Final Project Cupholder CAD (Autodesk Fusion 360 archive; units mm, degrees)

design "Final Project" references "Servo_motor", "Arcade Button_30mm", "EIP Cupholder PCB"
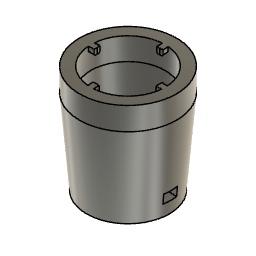
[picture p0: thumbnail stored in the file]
parameter "CupHolderBottomDiameter" = 76.2
parameter "CupHolderTopDiameter" = 88.9
parameter "CupHolderHeight" = 76.2
parameter "CupHolderThickness" = 10 comment "Only for visual CAD  purposes"
parameter "CupHolderTolerance" = 2 comment "Between cup holder and the mechanism case"
parameter "LidHeight" = 30
parameter "CupHolderCaseThickness" = 10
parameter "LockingMechanismProtrusionWidth" = 5
parameter "LockingMechanismTolerance" = 1
parameter "LockingMechanismProtrusionHeight" = 5
parameter "LockingMechanismProtrusionDistance" = 5
parameter "LockingMechanismAngle" = 20
parameter "ArcadeButtonDiameter" = 30
parameter "MirrorAttachmentCurlThickness" = 2
sketch "Sketch2" plane through (0, 0, 0) normal (0, 0, 1) x axis (1, 0, 0)
  circle C1 centre (0, 0) radius 38.1
  point P1 (0, 0)
  point P2 (0, 0)
  coincident P1 P2
  dimension "d3" diameter C1 = 76.2 (= "CupHolderBottomDiameter")
work_plane "WorkPlane1" sketch "Sketch2" AlongDistance 76.2 (= "CupHolderHeight")
sketch "Sketch3" plane through (0, 0, 76.2) normal (0, 0, 1) x axis (1, 0, 0)
  circle C1 centre (0, 0) radius 44.45
  point P1 (0, 0)
  point P2 (0, 0)
  coincident P1 P2
  dimension "d6" diameter C1 = 88.9 (= "CupHolderTopDiameter")
loft "Loft1" sketch "Sketch2" + "Sketch3"
sketch "Sketch4" plane through (0, 0, 0) normal (0, 0, 1) x axis (1, 0, 0)
  circle C1 centre (0, 0) radius 88.9
  point P1 (0, 0)
  point P2 (0, 0)
  coincident P1 P2
  dimension "d7" diameter C1 = 177.8 (= "CupHolderTopDiameter * 2")
extrude "Extrude1" new body sketch "Sketch4" along normal blind 76.2 (= "CupHolderHeight")
extrude "Extrude2" new body of existing geometry blind 10 (= "CupHolderThickness") bodies "CupHolder"
combine "Combine2"
combine "Combine1"
sketch "Sketch1" plane through (0, 0, 0) normal (0, 0, 1) x axis (1, 0, 0)
  circle C1 centre (0, 0) radius 44.45
  point P1 (0, 0)
  point P2 (0, 0)
  coincident P1 P2
  dimension "d15" diameter C1 = 88.9 (= "CupHolderTopDiameter")
extrude "Extrude1" new body sketch "Sketch1" along normal blind 76.2 (= "CupHolderHeight")
combine "Combine1"
copy_paste "CutPaste1"
offset_faces "OffsetFaces1"
extrude "Extrude2" add of existing geometry blind 30 (= "LidHeight")
shell "Shell2" innerThickness 10 (= "CupHolderThickness")
split "Split4" bodies "CupHolderCase"
sketch "Sketch4" plane through (0, 0, 96.2) normal (0, 0, -1) x axis (1, 0, 0)
  circle C1 centre (0, 0) radius 42.4431
  circle C2 centre (0, 0) radius 32.4431
extrude "Extrude4" new body sketch "Sketch4" profile of C2 along normal blind 20 (= "LidHeight - CupHolderThickness")
combine "Combine4"
sketch "Sketch5" plane through (0, 0, 76.2) normal (0, 0, -1) x axis (1, 0, 0)
  line L1 (0, -32.4431) -> (0, -36.9654)
  line L2 (3, -32.4431) -> (0, -32.4431)
  line L3 (3, -25.4431) -> (3, -32.4431)
  line L4 (0, -25.4431) -> (3, -25.4431)
  line L5 (-3, -32.4431) -> (0, -32.4431)
  line L6 (-3, -25.4431) -> (-3, -32.4431)
  line L7 (0, -25.4431) -> (-3, -25.4431)
  circle C1 centre (0, 0) radius 32.4431
  point P4 (0, -32.4431)
  point P8 (0, -32.4431)
  point P5 (3, -32.4431)
  point P9 (-3, -32.4431)
  point P6 (3, -25.4431)
  point P10 (-3, -25.4431)
  point P7 (0, -25.4431)
  point P11 (0, -25.4431)
  coincident C1 P4
  vertical L1
  tangent C1 L2
  perpendicular L1 L2
  perpendicular L2 L3
  perpendicular L3 L4
  symmetric P4 L1 P8
  symmetric L1 P5 P9
  symmetric L1 P6 P10
  symmetric L1 P7 P11
  dimension "d37" distance P4 P5 = 3 (= "LockingMechanismProtrusionWidth / 2 + LockingMechanismTolerance / 2")
  dimension "d39" distance P5 P6 = 7 (= "LockingMechanismProtrusionDistance + CupHolderTolerance")
extrude "Extrude5" cut sketch "Sketch5" profile of C1 L3 L4 L6 L7 against normal blind 20
sketch "Sketch6" plane through (0, 0, 96.2) normal (0, 0, -1) x axis (1, 0, 0)
  line L1 (3, -25.4431) -> (3, -32.3041)
  line L2 (-3, -25.4431) -> (3, -25.4431)
  line L3 (-3, -32.3041) -> (-3, -25.4431)
  line L4 (-8.702, -23.9087) -> (0, 0)
  line L5 (0, -25.4431) -> (0, 0)
  line L6 (-11.0962, -30.4865) -> (-8.702, -23.9087)
  line L7 (-3, -25.2656) -> (-3, -25.4431)
  arc A1 centre (0, 0) radius 32.4431 clockwise from (-3, -32.3041) to (3, -32.3041)
  circle C1 centre (0, 0) radius 42.4431
  arc A2 centre (0, 0) radius 25.4431 clockwise from (0, -25.4431) to (-8.702, -23.9087)
  point P9 (0, -25.4431)
  point P1 (0, 0)
  point P7 (0, 0)
  point P10 (-11.0962, -30.4865)
  point P6 (-3, -25.4431)
  point P11 (-3, -25.4431)
  point P12 (-3, -25.2656)
  midpoint L2 P9
  coincident P1 P7
  coincident A1 P10
  parallel L4 L6
  coincident P6 P11
  coincident A2 P12
  perpendicular L2 L7
  dimension "d43" angle L4 L5 = 20 (= "LockingMechanismAngle")
extrude "Extrude6" cut sketch "Sketch6" profile of A1 L3 A2 L6 L7 along normal blind 6 (= "LockingMechanismProtrusionHeight + LockingMechanismTolerance")
extrude "Extrude7" cut sketch "Sketch6" profile of L2 A2 L7 along normal blind 20
sketch "Sketch7" plane through (0, 0, 0) normal (0.9397, 0.342, 0) x axis (-0.342, 0.9397, 0)
  line L1 (25.4431, 96.2) -> (32.4431, 96.2)
  line L2 (25.4431, 90.2) -> (25.4431, 96.2)
  line L3 (32.4431, 90.2) -> (25.4431, 90.2)
  line L4 (32.4431, 96.2) -> (32.4431, 90.2)
  line L5 (32.4431, 91.2) -> (32.4431, 90.2)
  line L6 (25.4431, 91.2) -> (32.4431, 91.2)
  point P5 (32.4431, 90.2)
  point P6 (32.4431, 90.2)
  point P7 (32.4431, 91.2)
  point P8 (25.4431, 91.2)
  coincident P5 P6
  coincident L4 P7
  coincident L2 P8
  perpendicular L2 L6
  dimension "d48" distance P6 P7 = 1 (= "LockingMechanismTolerance")
loft "Loft3" sketch "Sketch7"
circular_pattern "C-Pattern1" TotalAngle 360
fillet "Fillet2" radius 1 1
sketch "Sketch8" plane through (0, 0, 96.2) normal (0, 0, 1) x axis (-1, 0, 0)
  line L1 (2.2086, -32.4642) -> (-0.2913, -32.4418)
  line L2 (2.2535, -27.4644) -> (2.2086, -32.4642)
  line L3 (-0.4431, -27.4402) -> (2.2535, -27.4644)
  line L4 (-0.4431, -27.4402) -> (-0.2913, -32.4418)
  line L5 (-2.7852, -32.6157) -> (-0.2913, -32.4418)
  line L6 (-3.1332, -27.6279) -> (-2.7852, -32.6157)
  line L7 (-0.4431, -27.4402) -> (-3.1332, -27.6279)
  circle C1 centre (0, 0) radius 32.4431
  circle C2 centre (0, 0) radius 42.4431
  point P3 (-0.2913, -32.4418)
  point P7 (-0.2913, -32.4418)
  point P4 (2.2086, -32.4642)
  point P8 (-2.7852, -32.6157)
  point P5 (2.2535, -27.4644)
  point P9 (-3.1332, -27.6279)
  point P6 (-0.4431, -27.4402)
  point P10 (-0.4431, -27.4402)
  coincident C1 P3
  tangent C1 L1
  perpendicular L1 L2
  perpendicular L2 L3
  symmetric P3 L4 P7
  symmetric P4 L4 P8
  symmetric P5 L4 P9
  symmetric P6 L4 P10
  dimension "d51" distance P3 P4 = 2.5 (= "LockingMechanismProtrusionWidth / 2")
  dimension "d52" distance P4 P5 = 5
extrude "Extrude8" add sketch "Sketch8" profile of C1 L2 L3 L6 L7 no distance stored
fillet "Fillet1" radius 1
circular_pattern "C-Pattern2" TotalAngle 360
sketch "Sketch9" plane through (0, 0, 106.2) normal (0, 0, 1) x axis (-1, 0, 0)
  line L1 (-13.5367, -40.2265) -> (0, 0)
  line L2 (-0.4435, -42.4408) -> (0, 0)
  line L3 (0, 0) -> (-7.0772, -41.8489)
  line L4 (-19.6113, -115.9654) -> (-7.0772, -41.8489)
  curve K1 (-7.4119, -43.8277) -> (-0.4435, -42.4408)
  curve K2 (-0.847, -42.4391) -> (-0.04, -42.4424)
  line L5 (-10.6726, -43.2763) -> (-7.4119, -43.8277)
  curve K3 (-9.0422, -43.552) -> (-5.7815, -44.1034)
  curve K4 (-7.4119, -43.8277) -> (-13.5367, -40.2265)
  curve K5 (-13.1551, -40.3576) -> (-13.9183, -40.0954)
  curve K6 (-5.7815, -44.1034) -> (-9.0422, -43.552)
  circle C1 centre (0, 0) radius 42.4431
  arc A1 centre (0, 0) radius 42.4431 clockwise from (-0.4435, -42.4408) to (-13.5367, -40.2265)
  point P5 (-0.4435, -42.4408)
  point P1 (0, 0)
  point P3 (0, 0)
  point P6 (-7.0772, -41.8489)
  point P7 (-7.0772, -41.8489)
  point P8 (0, 0)
  point P9 (-7.0772, -41.8489)
  point P12 (-7.4119, -43.8277)
  point P17 (-9.0422, -43.552)
  point P18 (-13.5367, -40.2265)
  point P11 (-4.9088, -86.9573)
  point P19 (-23.9577, -83.7359)
  point P20 (-7.4119, -43.8277)
  point P13 (-0.04, -42.4424)
  point P21 (-13.9183, -40.0954)
  point P14 (-0.847, -42.4391)
  point P22 (-13.1551, -40.3576)
  point P16 (-5.7815, -44.1034)
  point P23 (-9.0422, -43.552)
  point P24 (-5.7815, -44.1034)
  coincident C1 P5
  coincident P1 P3
  midpoint A1 P6
  coincident P6 P7
  coincident P1 P8
  coincident P6 P9
  parallel L3 L4
  coincident L4 P12
  midpoint P5 K2
  perpendicular L4 L5
  midpoint P12 K3
  midpoint L5 P17
  parallel L5 K3
  symmetric P5 L4 P18
  symmetric L4 P11 P19
  symmetric L4 P12 P20
  symmetric L4 P13 P21
  symmetric L4 P14 P22
  symmetric L4 P16 P23
  symmetric L4 P17 P24
  dimension "d64" angle L1 L2 = 18 (= "( 360 / NumGripsTopLid ) * 1 deg")
  dimension "d153" distance P8 P12 = 44.45 (= "CupHolderTopDiameter / 2")
extrude "Extrude9" new body sketch "Sketch9" profile of C1 K1 K4 against normal blind 10
combine "Combine6"
circular_pattern "C-Pattern4" TotalAngle 360
component_from_bodies "Body->Comp1"
component_from_bodies "Body->Comp2"
fillet "Fillet1" radius 1
fillet "Fillet2" radius 1
sketch "Sketch10" plane through (0, 0, 76.2) normal (0, 0, -1) x axis (1, 0, 0)
  line L1 (24.1136, -4) -> (31.1876, -4)
  line L2 (24.4431, 4) -> (24.4431, 0)
  line L3 (31.1876, 4) -> (24.4431, 4)
  line L4 (4, 24.1136) -> (4, 31.1876)
  line L5 (-4, 24.4431) -> (0, 24.4431)
  line L6 (-4, 31.1876) -> (-4, 24.4431)
  line L7 (-24.1136, 4) -> (-31.1876, 4)
  line L8 (-24.4431, -4) -> (-24.4431, 0)
  line L9 (-31.1876, -4) -> (-24.4431, -4)
  line L10 (-4, -24.1136) -> (-4, -31.1876)
  line L11 (4, -24.4431) -> (0, -24.4431)
  line L12 (4, -31.1876) -> (4, -24.4431)
  arc A1 centre (0, 0) radius 24.4431 clockwise from (24.4431, 0) to (24.1136, -4)
  arc A2 centre (0, 0) radius 31.4431 clockwise from (4, 31.1876) to (31.1876, 4)
  arc A3 centre (0, 0) radius 24.4431 clockwise from (0, 24.4431) to (4, 24.1136)
  arc A4 centre (0, 0) radius 31.4431 clockwise from (-31.1876, 4) to (-4, 31.1876)
  arc A5 centre (0, 0) radius 24.4431 clockwise from (-24.4431, 0) to (-24.1136, 4)
  arc A6 centre (0, 0) radius 31.4431 clockwise from (-4, -31.1876) to (-31.1876, -4)
  arc A7 centre (0, 0) radius 24.4431 clockwise from (0, -24.4431) to (-4, -24.1136)
  arc A8 centre (0, 0) radius 31.4431 clockwise from (31.1876, -4) to (4, -31.1876)
  circle C1 centre (0, 0) radius 22.5
  concentric A1 C1
  dimension "d155" diameter C1 = 45 (= "ArcadeButtonDiameter + 15 mm")
extrude "Extrude1" cut sketch "Sketch10" profile of C1 against normal blind 20
fillet "Fillet3" radius 1
fillet "Fillet4" radius 1
sketch "Sketch11" plane through (0, 0, 96.2) normal (0, 0, -1) x axis (1, 0, 0)
  circle C1 centre (0, 0) radius 21.5
  circle C2 centre (0, 0) radius 15
  point P1 (0, 0)
  point P3 (0, 0)
  coincident P1 P3
  dimension "d82" diameter C2 = 30 (= "ArcadeButtonDiameter")
extrude "Extrude2" cut sketch "Sketch11" profile of C2 against normal blind 10
component_insert "Component Insert1"
joint "Assemble1" alignAngle 0 alignOffsetX 0 alignOffsetY 0 alignOffsetZ 0
as_built_joint "As-built1" OffsetX 0 OffsetY 0 OffsetZ 0 AngleZ 0 AngleMaximum 0
joint "Assemble1" alignAngle 0 alignOffsetX 0 alignOffsetY 0 alignOffsetZ -130 DistanceMaximum 0 DistanceRest 0
base_feature "Base Feature1"
base_feature "Base Feature1"
base_feature "Base Feature1"
base_feature "Base Feature1"
base_feature "Base Feature1"
base_feature "Base Feature1"
base_feature "Base Feature1"
base_feature "Base Feature1"
base_feature "Base Feature1"
base_feature "Base Feature1"
base_feature "Base Feature1"
sketch "Sketch4" plane through (-0.0164, 0, -21.4157) normal (-0.0008, 0, -1) x axis (0, -1, 0)
  line L1 (-46.2621, -82.9366) -> (-46.2621, -20.9366)
  line L2 (51.0689, -82.9366) -> (-46.2621, -82.9366)
  line L3 (51.0689, -20.9366) -> (51.0689, -82.9366)
  line L4 (-46.2621, -20.9366) -> (51.0689, -20.9366)
  line L5 (8.573, -42.2771) -> (8.573, -31.2771)
  line L6 (-4.427, -44.2771) -> (6.573, -44.2771)
  line L7 (-6.427, -31.2771) -> (-6.427, -42.2771)
  line L8 (6.573, -29.2771) -> (-4.427, -29.2771)
  line L9 (-123.9966, -211.3616) -> (128.8034, -211.3616)
  line L10 (-123.9966, -20.9366) -> (-123.9966, -211.3616)
  line L11 (128.8034, -20.9366) -> (-123.9966, -20.9366)
  line L12 (128.8034, -211.3616) -> (128.8034, -20.9366)
  arc A1 centre (6.573, -42.2771) radius 2 clockwise from (8.573, -42.2771) to (6.573, -44.2771)
  arc A2 centre (-4.427, -42.2771) radius 2 clockwise from (-4.427, -44.2771) to (-6.427, -42.2771)
  arc A3 centre (-4.427, -31.2771) radius 2 clockwise from (-6.427, -31.2771) to (-4.427, -29.2771)
  arc A4 centre (6.573, -31.2771) radius 2 clockwise from (6.573, -29.2771) to (8.573, -31.2771)
  point P22 (2.4034, -20.9366)
  point P23 (2.4034, -20.9366)
  point P18 (128.8034, -211.3616)
  point P19 (-123.9966, -211.3616)
  point P20 (-123.9966, -20.9366)
  horizontal L9
  vertical L10
  horizontal L11
  vertical L12
  midpoint L11 P22
  midpoint L4 P23
  coincident P22 P23
  dimension "d128" distance P18 P19 = 252.8
  dimension "d129" distance P19 P20 = 190.425
extrude "Extrude2" new body sketch "Sketch4" profile of L1 L2 L3 L9 L10 L11 L12 against normal blind 2
combine "Combine3"
copy_paste_bodies "CutPasteBodies1"
remove_body "RemoveBody1"
sketch "Sketch5" plane through (-0.0164, 0, -21.4157) normal (-0.0008, 0, -1) x axis (0, -1, 0)
  line L1 (8.573, -42.2771) -> (8.573, -31.2771)
  line L2 (-4.427, -44.2771) -> (6.573, -44.2771)
  line L3 (-6.427, -31.2771) -> (-6.427, -42.2771)
  line L4 (6.573, -29.2771) -> (-4.427, -29.2771)
  line L5 (-123.9966, -20.9366) -> (128.8034, -20.9366)
  line L6 (-123.9966, -211.3616) -> (-123.9966, -20.9366)
  line L7 (128.8034, -211.3616) -> (-123.9966, -211.3616)
  line L8 (128.8034, -20.9366) -> (128.8034, -211.3616)
  line L9 (121.8034, -211.3616) -> (128.8034, -211.3616)
  line L10 (121.8034, -204.3616) -> (121.8034, -211.3616)
  line L11 (128.8034, -204.3616) -> (121.8034, -204.3616)
  line L12 (128.8034, -211.3616) -> (128.8034, -204.3616)
  arc A1 centre (6.573, -42.2771) radius 2 clockwise from (8.573, -42.2771) to (6.573, -44.2771)
  arc A2 centre (-4.427, -42.2771) radius 2 clockwise from (-4.427, -44.2771) to (-6.427, -42.2771)
  arc A3 centre (-4.427, -31.2771) radius 2 clockwise from (-6.427, -31.2771) to (-4.427, -29.2771)
  arc A4 centre (6.573, -31.2771) radius 2 clockwise from (6.573, -29.2771) to (8.573, -31.2771)
  circle C1 centre (121.8034, -204.3616) radius 2
  point P17 (128.8034, -211.3616)
  point P18 (128.8034, -211.3616)
  point P20 (121.8034, -204.3616)
  point P22 (121.8034, -204.3616)
  point P21 (128.8034, -204.3616)
  point P19 (121.8034, -211.3616)
  horizontal L9
  vertical L10
  horizontal L11
  vertical L12
  coincident P17 P18
  coincident P20 P22
  dimension "d132" distance P18 P21 = 7
  dimension "d133" distance P18 P19 = 7
  dimension "d134" diameter C1 = 4
extrude "Extrude1" cut sketch "Sketch5" profile of C1 against normal blind 2
work_plane "WorkPlane3"
work_plane "WorkPlane4"
mirror "Mirror1" mirrorStitchTolerance 0.1
mirror "Mirror2" mirrorStitchTolerance 0.1
extrude "Extrude2" cut of existing geometry blind -0.85 (= "-( 2 mm - 1.15 mm )")
sketch "Sketch6" plane through (-0.0157, 0, -20.5657) normal (-0.0008, 0, -1) x axis (0, -1, 0)
  line L1 (8.573, -42.2771) -> (8.573, -31.2771)
  line L2 (-4.427, -44.2771) -> (6.573, -44.2771)
  line L3 (-6.427, -31.2771) -> (-6.427, -42.2771)
  line L4 (6.573, -29.2771) -> (-4.427, -29.2771)
  line L5 (-123.9966, -20.9366) -> (128.8034, -20.9366)
  line L6 (-123.9966, -211.3616) -> (-123.9966, -20.9366)
  line L7 (128.8034, -211.3616) -> (-123.9966, -211.3616)
  line L8 (128.8034, -20.9366) -> (128.8034, -211.3616)
  line L9 (-123.9966, -211.3616) -> (128.8034, -211.3616)
  line L10 (-123.9966, -20.9366) -> (-123.9966, -211.3616)
  line L11 (128.8034, -20.9366) -> (-123.9966, -20.9366)
  line L12 (128.8034, -211.3616) -> (128.8034, -20.9366)
  line L13 (-98.9966, -185.8616) -> (103.8034, -185.8616)
  line L14 (-98.9966, -46.4366) -> (-98.9966, -185.8616)
  line L15 (103.8034, -46.4366) -> (-98.9966, -46.4366)
  line L16 (103.8034, -185.8616) -> (103.8034, -46.4366)
  line L17 (-98.9966, -46.4366) -> (103.8034, -185.8616)
  line L18 (103.8034, -46.4366) -> (-98.9966, -185.8616)
  line L19 (-123.9966, -20.9366) -> (128.8034, -211.3616)
  line L20 (128.8034, -20.9366) -> (-123.9966, -211.3616)
  circle C1 centre (-116.9966, -27.9366) radius 2
  circle C2 centre (-116.9966, -204.3616) radius 2
  circle C3 centre (121.8034, -27.9366) radius 2
  circle C4 centre (121.8034, -204.3616) radius 2
  arc A1 centre (6.573, -42.2771) radius 2 clockwise from (8.573, -42.2771) to (6.573, -44.2771)
  arc A2 centre (-4.427, -42.2771) radius 2 clockwise from (-4.427, -44.2771) to (-6.427, -42.2771)
  arc A3 centre (-4.427, -31.2771) radius 2 clockwise from (-6.427, -31.2771) to (-4.427, -29.2771)
  arc A4 centre (6.573, -31.2771) radius 2 clockwise from (6.573, -29.2771) to (8.573, -31.2771)
  point P19 (-123.9966, -20.9366)
  point P24 (-123.9966, -20.9366)
  point P21 (128.8034, -211.3616)
  point P22 (128.8034, -211.3616)
  point P30 (2.4034, -116.1491)
  point P31 (2.4034, -116.1491)
  point P26 (103.8034, -185.8616)
  point P27 (-98.9966, -185.8616)
  point P29 (103.8034, -46.4366)
  horizontal L9
  vertical L10
  horizontal L11
  vertical L12
  coincident P19 P24
  coincident P21 P22
  horizontal L13
  vertical L14
  horizontal L15
  vertical L16
  midpoint L18 P30
  midpoint L20 P31
  coincident P30 P31
  dimension "d143" distance P26 P27 = 202.8
  dimension "d144" distance P26 P29 = 139.425
extrude "Extrude3" new body sketch "Sketch6" profile of C1 C2 C3 C4 L1 A1 L2 A2 L3 A3 L4 A4 L5 L6 L7 L8 L9 L10 L11 L12 L13 L14 L15 L16 along normal blind 1.125
extrude "Extrude4" new body sketch "Sketch6" profile of L13 L14 L15 L16 along normal blind 1.125
move "Move1"
sketch "Sketch7" plane through (-0.0157, 0, -20.5657) normal (-0.0008, 0, -1) x axis (0, -1, 0)
  line L1 (8.573, -42.2771) -> (8.573, -31.2771)
  line L2 (-4.427, -44.2771) -> (6.573, -44.2771)
  line L3 (-6.427, -31.2771) -> (-6.427, -42.2771)
  line L4 (6.573, -29.2771) -> (-4.427, -29.2771)
  line L5 (-123.9966, -20.9366) -> (128.8034, -20.9366)
  line L6 (-123.9966, -211.3616) -> (-123.9966, -20.9366)
  line L7 (128.8034, -211.3616) -> (-123.9966, -211.3616)
  line L8 (128.8034, -20.9366) -> (128.8034, -211.3616)
  line L9 (-123.9966, -211.3616) -> (128.8034, -211.3616)
  line L10 (-123.9966, -20.9366) -> (-123.9966, -211.3616)
  line L11 (128.8034, -20.9366) -> (-123.9966, -20.9366)
  line L12 (128.8034, -211.3616) -> (128.8034, -20.9366)
  line L13 (-107.0466, -194.4116) -> (111.8534, -194.4116)
  line L14 (-107.0466, -37.8866) -> (-107.0466, -194.4116)
  line L15 (111.8534, -37.8866) -> (-107.0466, -37.8866)
  line L16 (111.8534, -194.4116) -> (111.8534, -37.8866)
  line L17 (-107.0466, -37.8866) -> (111.8534, -194.4116)
  line L18 (111.8534, -37.8866) -> (-107.0466, -194.4116)
  line L19 (-123.9966, -20.9366) -> (128.8034, -211.3616)
  line L20 (128.8034, -20.9366) -> (-123.9966, -211.3616)
  circle C1 centre (-116.9966, -27.9366) radius 2
  circle C2 centre (-116.9966, -204.3616) radius 2
  circle C3 centre (121.8034, -27.9366) radius 2
  circle C4 centre (121.8034, -204.3616) radius 2
  arc A1 centre (6.573, -42.2771) radius 2 clockwise from (8.573, -42.2771) to (6.573, -44.2771)
  arc A2 centre (-4.427, -42.2771) radius 2 clockwise from (-4.427, -44.2771) to (-6.427, -42.2771)
  arc A3 centre (-4.427, -31.2771) radius 2 clockwise from (-6.427, -31.2771) to (-4.427, -29.2771)
  arc A4 centre (6.573, -31.2771) radius 2 clockwise from (6.573, -29.2771) to (8.573, -31.2771)
  point P19 (-123.9966, -20.9366)
  point P24 (-123.9966, -20.9366)
  point P21 (128.8034, -211.3616)
  point P22 (128.8034, -211.3616)
  point P30 (2.4034, -116.1491)
  point P31 (2.4034, -116.1491)
  point P26 (111.8534, -194.4116)
  point P27 (-107.0466, -194.4116)
  point P29 (111.8534, -37.8866)
  horizontal L9
  vertical L10
  horizontal L11
  vertical L12
  coincident P19 P24
  coincident P21 P22
  horizontal L13
  vertical L14
  horizontal L15
  vertical L16
  midpoint L18 P30
  midpoint L20 P31
  coincident P30 P31
  dimension "d149" distance P26 P27 = 218.9
  dimension "d150" distance P26 P29 = 156.525
extrude "Extrude3" new body sketch "Sketch7" profile of C1 C2 C3 C4 L1 L3 A3 L4 A4 L5 L6 L7 L8 L9 L10 L11 L12 L13 L14 L15 L16 along normal blind 1.15
copy_paste_bodies "CutPasteBodies2"
sketch "pcb-sketch" plane through (0, 0, 183.1) normal (0, 0, -1) x axis (1, 0, 0)
  circle C1 centre (0, 0) radius 15
  circle C2 centre (0, 0) radius 21.5
  circle C3 centre (0, 0) radius 20.5
  dimension "d156" = -1
component_insert "Component Insert5"
step "Context"
sketch "Sketch9" plane through (0, 0, 183.1) normal (0, 0, -1) x axis (1, 0, 0)
  line L1 (-8, 0) -> (0, 0)
  point P1 (0, 0)
  point P2 (0, 0)
  coincident P1 P2
  horizontal L1
work_plane "WorkPlane5"
sketch "Sketch10" plane through (25.4431, 0, 164.1) normal (0, 1, 0) x axis (1, 0, 0)
  line L1 (-25.4431, -24) -> (-25.4431, -19)
  point P2 (-25.4431, -19)
  point P3 (-25.4431, -19)
  coincident P2 P3
  vertical L1
remove_instance "RemoveInstance1"
remove_instance "RemoveInstance2"
remove_instance "RemoveInstance3"
remove_instance "RemoveInstance4"
remove_instance "RemoveInstance5"
remove_instance "RemoveInstance6"
remove_instance "RemoveInstance7"
remove_instance "RemoveInstance8"
remove_instance "RemoveInstance9"
remove_instance "RemoveInstance10"
remove_instance "RemoveInstance11"
remove_instance "RemoveInstance12"
remove_instance "RemoveInstance13"
component_insert "Component Insert6"
copy_paste "CutPaste1"
position "Position2"
sketch "Sketch11" plane through (0, 0, 0) normal (1, 0, 0) x axis (0, 1, 0)
  line L1 (-6, 107.3995) -> (6, 107.3995)
  line L2 (-6, 99.3995) -> (-6, 107.3995)
  line L3 (6, 99.3995) -> (-6, 99.3995)
  line L4 (6, 107.3995) -> (6, 99.3995)
  line L5 (-6, 99.3995) -> (6, 107.3995)
  line L6 (6, 99.3995) -> (-6, 107.3995)
  point P6 (0, 103.3995)
  point P4 (-6, 99.3995)
  point P5 (6, 99.3995)
  point P3 (-6, 107.3995)
  horizontal L1
  perpendicular L1 L2
  parallel L1 L3
  parallel L2 L4
  coincident L5 P6
  coincident L6 P6
  dimension "d157" distance P4 P5 = 12
  dimension "d158" distance P3 P4 = 8
extrude "Extrude1" cut sketch "Sketch11" profile of L1 L2 L3 L4 along normal blind 100
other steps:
base_feature "Base Feature1" bodies "CupHolderCase"
base_feature "Base Feature2"
base_feature "Base Feature3"
base_feature "Base Feature1" bodies "Lid"
create_component "CreateComponent1"
create_component "CreateComponent1"
remove_instance "RemoveInstance1"
create_component "CreateComponent1"
remove_body "RemoveBody2"
create_component "CreateComponent2"
remove_body "RemoveBody3"
joint_origin "JointOrigin1"
joint_origin "JointOrigin3"
joint_origin "JointOrigin3"
create_component "CreateComponent1"
create_component "CreateComponent2"
create_component "CreateComponent3"
create_component "CreateComponent4"
create_component "CreateComponent5"
create_component "CreateComponent6"
create_component "CreateComponent7"
create_component "CreateComponent8"
create_component "CreateComponent9"
create_component "CreateComponent10"
create_component "CreateComponent11"
create_component "CreateComponent3"
remove_body "RemoveBody2"
remove_body "RemoveBody3"
remove_body "RemoveBody4"
remove_instance "RemoveInstance1"
named bodies: "CupHolder", "Lid", "CupHolderCase"

design "Servo_motor"
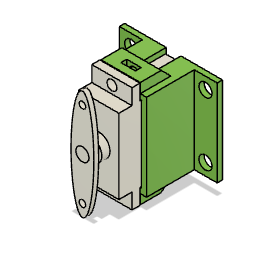
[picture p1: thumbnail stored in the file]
parameter "servo_height" = 22.8
parameter "servo_width" = 12.25
parameter "servo_length" = 22.8
parameter "servo_ears_width" = 4.745 (= "( ( 32.29 - 22.8 ) / 2 ) * 1 mm")
parameter "servo_ears_holes" = 3
parameter "servo_ears_thickness" = 2.44
parameter "servo_axle_diameter" = 6.85
parameter "servo_axle_length" = 5
parameter "servo_enclosure_margin" = 0.2
parameter "servo_enclosure_wall_thickness" = 1.6
parameter "servo_enclosure_ears_width" = 7
parameter "servo_enclosure_ears_screws" = 4
parameter "servo_ears_shift" = 4
parameter "servo_enclosure_cable_hole_height" = 6.5
parameter "servo_enclosure_cable_hole_width" = 4.5
parameter "d1322" = 0
parameter "d1323" = 0
parameter "d1324" = 0
parameter "d1325" = 0
parameter "d1609" = 0
parameter "d1610" = 0
parameter "d1611" = 0
parameter "d1612" = 0
parameter "d1621" = 0
parameter "d1622" = 0
parameter "d1623" = 0
parameter "d1624" = 0
parameter "d1698" = 0
parameter "d1699" = 0
parameter "d1700" = 0
parameter "d1701" = 0
parameter "d1706" = 0
parameter "d1707" = 0
parameter "d1708" = 0
parameter "d1709" = 0
parameter "d1714" = 0
parameter "d1715" = 0
parameter "d1716" = 0
parameter "d1717" = 0
parameter "d1726" = 0
parameter "d1727" = 0
parameter "d1728" = 0
parameter "d1729" = 0
base_feature "Base Feature1"
sketch "Sketch1" plane through (0, 0, 6) normal (0, 0, 1) x axis (1, 0, 0)
  line L1 (62.5, -47) -> (22.5, -47)
  line L2 (62.5, -53) -> (62.5, -47)
  line L3 (22.5, -53) -> (62.5, -53)
  line L4 (22.5, -47) -> (22.5, -53)
  line L5 (62.5, 103) -> (22.5, 103)
  line L6 (62.5, 97) -> (62.5, 103)
  line L7 (22.5, 97) -> (62.5, 97)
  line L8 (22.5, 103) -> (22.5, 97)
  line L9 (-98.7963, 175) -> (-27.5, 120)
  line L10 (-150, 175) -> (-98.7963, 175)
  line L11 (-150, -175) -> (-150, 175)
  line L12 (150, -175) -> (-150, -175)
  line L13 (150, 175) -> (150, -175)
  line L14 (98.7963, 175) -> (150, 175)
  line L15 (27.5, 120) -> (98.7963, 175)
  line L16 (-27.5, 120) -> (27.5, 120)
  line L17 (22.5, -3) -> (62.5, -3)
  line L18 (22.5, 3) -> (22.5, -3)
  line L19 (62.5, 3) -> (22.5, 3)
  line L20 (62.5, -3) -> (62.5, 3)
  line L21 (-22.5, -97) -> (-62.5, -97)
  line L22 (-22.5, -103) -> (-22.5, -97)
  line L23 (-62.5, -103) -> (-22.5, -103)
  line L24 (-62.5, -97) -> (-62.5, -103)
  line L25 (-22.5, 103) -> (-62.5, 103)
  line L26 (-22.5, 97) -> (-22.5, 103)
  line L27 (-62.5, 97) -> (-22.5, 97)
  line L28 (-62.5, 103) -> (-62.5, 97)
  line L29 (-22.5, 53) -> (-62.5, 53)
  line L30 (-22.5, 47) -> (-22.5, 53)
  line L31 (-62.5, 47) -> (-22.5, 47)
  line L32 (-62.5, 53) -> (-62.5, 47)
  line L33 (62.5, 53) -> (22.5, 53)
  line L34 (62.5, 47) -> (62.5, 53)
  line L35 (22.5, 47) -> (62.5, 47)
  line L36 (22.5, 53) -> (22.5, 47)
  line L37 (-22.5, -147) -> (-62.5, -147)
  line L38 (-22.5, -153) -> (-22.5, -147)
  line L39 (-62.5, -153) -> (-22.5, -153)
  line L40 (-62.5, -147) -> (-62.5, -153)
  line L41 (-22.5, -47) -> (-62.5, -47)
  line L42 (-22.5, -53) -> (-22.5, -47)
  line L43 (-62.5, -53) -> (-22.5, -53)
  line L44 (-62.5, -47) -> (-62.5, -53)
  line L45 (-22.5, 3) -> (-62.5, 3)
  line L46 (-22.5, -3) -> (-22.5, 3)
  line L47 (-62.5, -3) -> (-22.5, -3)
  line L48 (-62.5, 3) -> (-62.5, -3)
  line L49 (62.5, -97) -> (22.5, -97)
  line L50 (62.5, -103) -> (62.5, -97)
  line L51 (22.5, -103) -> (62.5, -103)
  line L52 (22.5, -97) -> (22.5, -103)
  line L53 (62.5, -147) -> (22.5, -147)
  line L54 (62.5, -153) -> (62.5, -147)
  line L55 (22.5, -153) -> (62.5, -153)
  line L56 (22.5, -147) -> (22.5, -153)
  line L57 (80, 2) -> (80, -118)
  line L58 (120, 12) -> (90, 12)
  line L59 (130, -118) -> (130, 2)
  line L60 (90, -128) -> (120, -128)
  line L61 (-80, -118) -> (-80, 2)
  line L62 (-120, -128) -> (-90, -128)
  line L63 (-130, 2) -> (-130, -118)
  line L64 (-90, 12) -> (-120, 12)
  line L65 (-6.125, 120) -> (6.125, 120)
  line L66 (-6.125, 97.2) -> (-6.125, 120)
  line L67 (6.125, 97.2) -> (-6.125, 97.2)
  line L68 (6.125, 120) -> (6.125, 97.2)
  arc A1 centre (90, 2) radius 10 clockwise from (80, 2) to (90, 12)
  arc A2 centre (120, 2) radius 10 clockwise from (120, 12) to (130, 2)
  arc A3 centre (120, -118) radius 10 clockwise from (130, -118) to (120, -128)
  arc A4 centre (90, -118) radius 10 clockwise from (90, -128) to (80, -118)
  circle C1 centre (-132.5, 155) radius 3
  circle C2 centre (132.5, 155) radius 3
  circle C3 centre (132.5, -155) radius 3
  arc A5 centre (-90, -118) radius 10 clockwise from (-80, -118) to (-90, -128)
  arc A6 centre (-120, -118) radius 10 clockwise from (-120, -128) to (-130, -118)
  arc A7 centre (-120, 2) radius 10 clockwise from (-130, 2) to (-120, 12)
  arc A8 centre (-90, 2) radius 10 clockwise from (-90, 12) to (-80, 2)
  circle C4 centre (-132.5, -155) radius 3
  point P86 (6.125, 120)
  point P87 (-6.125, 120)
  point P89 (6.125, 97.2)
  horizontal L65
  vertical L66
  horizontal L67
  vertical L68
  coincident L16 P86
  midpoint L16 L65
  dimension "d928" distance P86 P87 = 12.25 (= "servo_width")
  dimension "d929" distance P86 P89 = 22.8 (= "servo_length")
extrude "Extrude1" new body sketch "Sketch1" profile of L16 L65 L66 L67 L68 along normal blind 22.8 (= "servo_height")
sketch "Sketch2" plane through (0, 0, 28.8) normal (0, 0, 1) x axis (1, 0, 0)
  line L1 (6.125, 120) -> (6.125, 97.2)
  line L2 (-6.125, 120) -> (6.125, 120)
  line L3 (-6.125, 97.2) -> (-6.125, 120)
  line L4 (6.125, 97.2) -> (-6.125, 97.2)
  line L5 (6.125, 97.2) -> (-6.125, 120)
  line L6 (-6.125, 124.745) -> (-6.125, 120)
  line L7 (6.125, 124.745) -> (-6.125, 124.745)
  line L8 (6.125, 120) -> (6.125, 124.745)
  line L9 (-6.125, 92.455) -> (-6.125, 97.2)
  line L10 (6.125, 92.455) -> (-6.125, 92.455)
  line L11 (6.125, 97.2) -> (6.125, 92.455)
  line L12 (6.125, 120) -> (-6.125, 124.745)
  line L13 (6.125, 92.455) -> (-6.125, 97.2)
  circle C1 centre (0, 108.6) radius 2
  circle C2 centre (0, 122.3725) radius 1.5
  circle C3 centre (0, 94.8275) radius 1.5
  circle C4 centre (0, 108.6) radius 3.425
  point P4 (-6.125, 120)
  point P7 (-6.125, 120)
  point P2 (6.125, 97.2)
  point P8 (6.125, 97.2)
  point P6 (0, 108.6)
  point P9 (-6.125, 120)
  point P3 (6.125, 120)
  point P12 (6.125, 120)
  point P5 (-6.125, 97.2)
  point P13 (-6.125, 97.2)
  point P16 (6.125, 97.2)
  point P17 (0, 122.3725)
  point P18 (0, 94.8275)
  coincident P4 P7
  coincident P2 P8
  midpoint P6 L5
  coincident P4 P9
  perpendicular L2 L6
  perpendicular L1 L7
  coincident P3 P12
  perpendicular L7 L8
  coincident P5 P13
  perpendicular L4 L9
  perpendicular L1 L10
  coincident P2 P16
  perpendicular L4 L11
  midpoint L12 P17
  midpoint L13 P18
  concentric C1 C4
  dimension "d956" diameter C1 = 4
  dimension "d1202" distance L2 L7 = 4.745 (= "servo_ears_width")
  dimension "d1203" distance L4 L10 = 4.745 (= "servo_ears_width")
  dimension "d1204" diameter C2 = 3 (= "servo_ears_holes")
  dimension "d1205" diameter C3 = 3 (= "servo_ears_holes")
  dimension "d1208" diameter C4 = 6.85 (= "servo_axle_diameter")
extrude "Extrude2" add sketch "Sketch2" profile of C1 along normal blind 5 (= "servo_axle_length")
extrude "Extrude5" add sketch "Sketch2" profile of C1 C4 along normal blind 2.5 (= "servo_axle_length / 2")
sketch "Sketch3" plane through (0, 0, 33.8) normal (0, 0, 1) x axis (1, 0, 0)
  curve K1 (0, 125.3267) -> (0, 91.8733)
  curve K2 (-3.4771, 108.6) -> (3.4771, 108.6)
  circle C1 centre (0, 108.6) radius 2
  closed curve K3 centre (0, 108.6)
  circle C2 centre (0, 121.6) radius 1
  circle C3 centre (0, 95.6) radius 1
  point P4 (0, 91.8733)
  point P5 (0, 125.3267)
  point P6 (3.4771, 108.6)
  point P7 (-3.4771, 108.6)
  point P8 (0, 121.6)
  point P9 (0, 95.6)
  point P2 (0, 108.6)
  point P3 (0, 108.6)
  concentric C1 K3
  vertical K1
  coincident K3 P4
  coincident K3 P5
  coincident K3 P6
  coincident K3 P7
  coincident K1 P8
  coincident K1 P9
  dimension "d961" diameter C2 = 2
  dimension "d962" diameter C3 = 2
  dimension "d963" distance P2 P8 = 13
  dimension "d964" distance P3 P9 = 13 (= "d963")
extrude "Extrude3" new body sketch "Sketch3" profile of C1 K3 C2 C3 no distance stored
extrude "Extrude4" add sketch "Sketch2" profile of L2 L4 L6 L7 L8 L9 L10 L11 C2 C3 no distance stored
component_from_bodies "Body->Comp1"
component_from_bodies "Body->Comp2"
joint "Assemble1" alignAngle 0 alignOffsetX 0 alignOffsetY 0 alignOffsetZ 0
position "Position13"
position "Position1"
sketch "Sketch3" plane through (0, -5, 88) normal (0, 0, -1) x axis (-1, 0, 0)
  line L1 (-6.125, 87.2) -> (-6.125, 110)
  line L2 (6.125, 87.2) -> (-6.125, 87.2)
  line L3 (6.125, 110) -> (6.125, 87.2)
  line L4 (-6.125, 110) -> (6.125, 110)
  line L5 (-6.125, 114.745) -> (-6.125, 110)
  line L6 (6.125, 114.745) -> (-6.125, 114.745)
  line L7 (6.125, 110) -> (6.125, 114.745)
  line L8 (-6.125, 82.455) -> (6.125, 82.455)
  line L9 (-6.125, 110) -> (6.125, 110)
  line L10 (6.125, 87.2) -> (-6.125, 87.2)
  line L11 (6.325, 87) -> (-6.325, 87)
  line L12 (6.325, 110.2) -> (6.325, 87)
  line L13 (-6.325, 110.2) -> (6.325, 110.2)
  line L14 (-6.325, 87) -> (-6.325, 110.2)
  line L15 (-7.925, 85.4) -> (-7.925, 111.8)
  line L16 (7.925, 85.4) -> (-7.925, 85.4)
  line L17 (7.925, 111.8) -> (7.925, 85.4)
  line L18 (-7.925, 111.8) -> (7.925, 111.8)
  line L19 (14.925, 111.8) -> (7.925, 111.8)
  line L20 (14.925, 85.4) -> (14.925, 111.8)
  line L21 (7.925, 85.4) -> (14.925, 85.4)
  line L22 (-14.925, 85.4) -> (-7.925, 85.4)
  line L23 (-14.925, 111.8) -> (-14.925, 85.4)
  line L24 (-7.925, 111.8) -> (-14.925, 111.8)
  line L25 (2.4027, 121.8) -> (-2.4027, 121.8)
  line L26 (2.4027, 111.8) -> (2.4027, 121.8)
  line L27 (-2.4027, 111.8) -> (2.4027, 111.8)
  line L28 (-2.4027, 121.8) -> (-2.4027, 111.8)
  line L29 (-6.125, 110) -> (6.125, 110)
  line L30 (6.125, 82.455) -> (6.125, 87.2)
  line L31 (-6.125, 87.2) -> (-6.125, 82.455)
  line L32 (6.125, 87.2) -> (-6.125, 87.2)
  circle C1 centre (0, 84.8275) radius 1.5
  circle C2 centre (0, 112.3725) radius 1.5
  circle C3 centre (11.325, 108.2) radius 2
  circle C4 centre (11.325, 89) radius 2
  circle C5 centre (-11.325, 89) radius 2
  circle C6 centre (-11.325, 108.2) radius 2
  point P36 (0, 111.8)
  point P28 (11.325, 108.2)
  point P29 (11.325, 89)
  point P30 (-11.325, 89)
  point P31 (-11.325, 108.2)
  point P32 (-2.4027, 121.8)
  point P35 (-2.4027, 111.8)
  perpendicular L17 L19
  perpendicular L16 L20
  perpendicular L17 L21
  perpendicular L12 L22
  perpendicular L18 L23
  perpendicular L15 L24
  horizontal L25
  vertical L26
  horizontal L27
  vertical L28
  midpoint L27 P36
  midpoint L18 P36
  dimension "d1211" = 0.2 (= "servo_enclosure_margin")
  dimension "d1213" = 1.8 (= "servo_enclosure_margin + servo_enclosure_wall_thickness")
  dimension "d1216" distance L17 L20 = 7 (= "servo_enclosure_ears_width")
  dimension "d1217" distance L15 L23 = 7 (= "d1216")
  dimension "d1248" diameter C3 = 4 (= "servo_enclosure_ears_screws")
  dimension "d1250" distance L19 P28 = 3.6 (= "servo_enclosure_ears_screws / 2 + servo_enclosure_wall_thickness")
  dimension "d1251" distance L20 P28 = 3.6 (= "d1250")
  dimension "d1252" diameter C6 = 4 (= "d1248")
  dimension "d1253" diameter C5 = 4 (= "d1248")
  dimension "d1254" diameter C4 = 4 (= "d1248")
  dimension "d1255" distance L20 P29 = 3.6 (= "d1250")
  dimension "d1256" distance L21 P29 = 3.6 (= "d1250")
  dimension "d1257" distance L22 P30 = 3.6 (= "d1250")
  dimension "d1258" distance L23 P30 = 3.6 (= "d1250")
  dimension "d1259" distance L24 P31 = 3.6 (= "d1250")
  dimension "d1260" distance L23 P31 = 3.6 (= "d1250")
  dimension "d1273" distance P32 P35 = 10
  dimension "d1261" OffsetX = 0
  dimension "d1262" OffsetY = 0
  dimension "d1263" OffsetZ = 0
  dimension "d1264" AngleZ = 0
  dimension "d1298" OffsetX = 0
  dimension "d1299" OffsetY = 0
  dimension "d1300" OffsetZ = 0
  dimension "d1301" AngleZ = 0
  dimension "d1597" OffsetX = 0
  dimension "d1598" OffsetY = 0
  dimension "d1599" OffsetZ = 0
  dimension "d1600" AngleZ = 0
extrude "Extrude1" new body sketch "Sketch3" profile of C1 C2 L5 L7 L14 L13 L12 L11 L17 L16 L18 L15 L27 L30 L31 no distance stored
extrude "Extrude2" add sketch "Sketch3" profile of L17 L15 L19 L20 L21 L22 L23 L24 C3 C4 C5 C6 no distance stored
sketch "Sketch4" plane through (0, 106.8, 0) normal (0, 1, 0) x axis (-1, 0, 0)
  line L1 (14.925, 88) -> (-14.925, 88)
  line L2 (14.925, 89.6) -> (14.925, 88)
  line L3 (7.925, 89.6) -> (14.925, 89.6)
  line L4 (7.925, 104.16) -> (7.925, 89.6)
  line L5 (-7.925, 104.16) -> (7.925, 104.16)
  line L6 (-7.925, 89.6) -> (-7.925, 104.16)
  line L7 (-14.925, 89.6) -> (-7.925, 89.6)
  line L8 (-14.925, 88) -> (-14.925, 89.6)
  line L9 (6, 97.76) -> (7.925, 97.76)
  line L10 (6, 104.16) -> (6, 97.76)
  line L11 (-6, 104.16) -> (-6, 97.76)
  line L12 (-7.925, 97.76) -> (-6, 97.76)
  line L13 (-6, 97.76) -> (6, 97.76)
  line L14 (-6, 104.16) -> (6, 97.76)
  line L15 (2.2, 100.085) -> (-2.2, 100.085)
  line L16 (2.2, 101.835) -> (2.2, 100.085)
  line L17 (-2.2, 101.835) -> (2.2, 101.835)
  line L18 (-2.2, 100.085) -> (-2.2, 101.835)
  line L19 (2.2, 101.835) -> (-2.2, 100.085)
  line L20 (-2.2, 101.835) -> (2.2, 100.085)
  line L21 (-2.25, 88) -> (2.25, 88)
  line L22 (-2.25, 94.5) -> (-2.25, 88)
  line L23 (2.25, 94.5) -> (-2.25, 94.5)
  line L24 (2.25, 88) -> (2.25, 94.5)
  point P10 (7.925, 97.76)
  point P11 (6, 97.76)
  point P12 (6, 104.16)
  point P13 (-6, 97.76)
  point P14 (-6, 104.16)
  point P15 (-7.925, 97.76)
  point P20 (0, 100.96)
  point P21 (2.25, 88)
  point P17 (2.2, 100.085)
  point P18 (2.2, 101.835)
  point P19 (-2.2, 101.835)
  point P24 (2.25, 94.5)
  point P23 (-2.25, 94.5)
  coincident L4 P10
  perpendicular L4 L9
  coincident L9 P11
  coincident L5 P12
  perpendicular L5 L10
  coincident L9 P13
  coincident L5 P14
  perpendicular L5 L11
  coincident L6 P15
  perpendicular L6 L12
  equal L9 L12
  perpendicular L15 L16
  parallel L15 L17
  parallel L16 L18
  horizontal L15
  coincident L19 P20
  coincident L20 P20
  midpoint L14 P20
  horizontal L21
  vertical L22
  horizontal L23
  vertical L24
  coincident L1 P21
  midpoint L1 L21
  dimension "d1223" distance L5 L9 = 6.4 (= "servo_enclosure_wall_thickness * 4")
  dimension "d1227" distance L10 L11 = 12 (= "servo_ears_holes * 4")
  dimension "d1235" distance P17 P18 = 1.75
  dimension "d1236" distance P18 P19 = 4.4
  dimension "d1332" distance P21 P24 = 6.5 (= "servo_enclosure_cable_hole_height")
  dimension "d1333" distance P23 P24 = 4.5 (= "servo_enclosure_cable_hole_width")
extrude "Extrude3" add sketch "Sketch4" profile of L5 L10 L11 L13 no distance stored
extrude "Extrude7" sketch "Sketch4" profile of L5 L10 L11 L13 L15 L16 L17 L18 no distance stored
chamfer "Chamfer2" distance 2.945 (= "servo_ears_width - servo_enclosure_wall_thickness - servo_enclosure_margin")
sketch "Sketch6" plane through (0, -5, 104.36) normal (0, 0, -1) x axis (-1, 0, 0)
  line L1 (-6.125, 114.745) -> (6.125, 114.745)
  line L2 (-6.125, 110) -> (-6.125, 114.745)
  line L3 (6.125, 110) -> (-6.125, 110)
  line L4 (6.125, 114.745) -> (6.125, 110)
  line L5 (6.125, 87.2) -> (6.125, 82.455)
  line L6 (-6.125, 87.2) -> (6.125, 87.2)
  line L7 (-6.125, 82.455) -> (-6.125, 87.2)
  line L8 (6.125, 82.455) -> (-6.125, 82.455)
  circle C1 centre (0, 112.3725) radius 1.5
  circle C2 centre (0, 84.8275) radius 1.5
joint_origin "JointOrigin2" OffsetX 0 OffsetY 0 OffsetZ 0 AngleZ 0
joint_origin "JointOrigin3" OffsetX 0 OffsetY 0 OffsetZ 0 AngleZ 0
extrude "Extrude8" cut sketch "Sketch6" profile of C1 C2 along normal blind 10
extrude "Extrude9" cut sketch "Sketch4" profile of L15 L16 L17 L18 no distance stored
joint "Assemble2" alignAngle 0 alignOffsetX 0 alignOffsetY 0 alignOffsetZ 0
extrude "Extrude1" cut sketch "Sketch4" profile of L1 L21 L22 L23 L24 no distance stored
sketch "Sketch7" plane through (0, 0, 94.5) normal (0, 0, -1) x axis (-1, 0, 0)
  line L1 (2.25, 105.2) -> (-2.25, 105.2)
  line L2 (2.25, 106.8) -> (2.25, 105.2)
  line L3 (1.3865, 106.8) -> (2.25, 106.8)
  line L4 (-2.25, 106.8) -> (-1.3865, 106.8)
  line L5 (-2.25, 105.2) -> (-2.25, 106.8)
  line L6 (-2.25, 105.2) -> (-2.25, 106.8)
  line L7 (2.25, 106.8) -> (2.25, 105.2)
  line L8 (1.3865, 106.8) -> (-1.3865, 106.8)
  line L9 (1.3865, 105.2) -> (1.3865, 106.8)
  line L10 (-1.3865, 105.2) -> (1.3865, 105.2)
  line L11 (-1.3865, 106.8) -> (-1.3865, 105.2)
  line L12 (1.3408, 80.5) -> (-1.3408, 80.5)
  line L13 (1.3408, 81.7) -> (1.3408, 80.5)
  line L14 (-1.3408, 81.7) -> (1.3408, 81.7)
  line L15 (-1.3408, 80.5) -> (-1.3408, 81.7)
  line L16 (-2.25, 106.8) -> (-1.3865, 106.8)
  line L17 (2.25, 105.2) -> (-2.25, 105.2)
  line L18 (1.3865, 106.8) -> (2.25, 106.8)
  arc A1 centre (0, 107.3725) radius 1.5 clockwise from (1.3865, 106.8) to (-1.3865, 106.8)
  arc A2 centre (0, 107.3725) radius 1.5 clockwise from (1.3865, 106.8) to (-1.3865, 106.8)
  point P5 (1.3865, 106.8)
  point P14 (1.3865, 106.8)
  point P6 (-1.3865, 106.8)
  point P13 (-1.3865, 106.8)
  perpendicular L8 L9
  parallel L8 L10
  parallel L9 L11
  coincident P5 P14
  parallel L3 L8
  coincident P6 P13
  perpendicular L12 L13
  parallel L12 L14
  parallel L13 L15
  perpendicular L11 L12
  collinear L10 L17
extrude "Extrude11" cut sketch "Sketch7" profile of L1 L2 L3 A1 L4 L5 L6 L7 L9 L10 L11 A2 L16 L17 L18 against normal blind 16
fillet "Fillet2" radius 1.6 (= "servo_enclosure_wall_thickness")
ground "Ground1"
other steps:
base_feature "Base Feature1" OffsetX 0 OffsetY 0 OffsetZ 0 AngleZ 0 OffsetX 0 OffsetY 0 OffsetZ 0 AngleZ 0 OffsetX 0 OffsetY 0 OffsetZ 0 AngleZ 0 OffsetX 0 OffsetY 0 OffsetZ 0 AngleZ 0 OffsetX 0 OffsetY 0 OffsetZ 0 AngleZ 0 OffsetX 0 OffsetY 0 OffsetZ 0 AngleZ 0 OffsetX 0 OffsetY 0 OffsetZ 0 AngleZ 0
base_feature "Base Feature1" OffsetX 0 OffsetY 0 OffsetZ 0 AngleZ 0 OffsetX 0 OffsetY 0 OffsetZ 0 AngleZ 0 OffsetX 0 OffsetY 0 OffsetZ 0 AngleZ 0 OffsetX 0 OffsetY 0 OffsetZ 0 AngleZ 0 OffsetX 0 OffsetY 0 OffsetZ 0 AngleZ 0 OffsetX 0 OffsetY 0 OffsetZ 0 AngleZ 0
extrude "Extrude10" cut sketch "Sketch4" profile of L1 L21 L22 L23 L24 no distance stored
create_component "CreateComponent1"
remove_body "RemoveBody1"
create_component "CreateComponent2"
remove_body "RemoveBody2"
joint_origin "JointOrigin3" OffsetX 0 OffsetY 0 OffsetZ 0 AngleZ 0
joint_origin "JointOrigin4" OffsetX 0 OffsetY 0 OffsetZ 0 AngleZ 0
create_component "CreateComponent3"
joint_origin "JointOrigin5" OffsetX 0 OffsetY 0 OffsetZ 0 AngleZ 0
joint_origin "JointOrigin7" OffsetX 0 OffsetY 0 OffsetZ 0 AngleZ 0

design "Arcade Button_30mm"
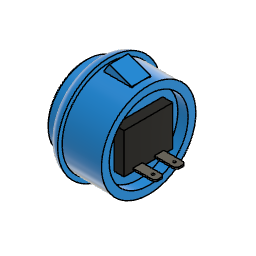
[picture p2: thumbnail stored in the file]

design "EIP Cupholder PCB"
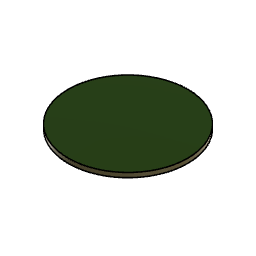
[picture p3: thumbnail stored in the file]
derived_context "DerivedContext1"
sketch "Outline" plane through (0, 0, 0) normal (0, 0, 1) x axis (1, 0, 0)
step sketch "pcb-sketch"
canvas "Canvas1" bodies "Board"
canvas "Canvas2" bodies "Board"
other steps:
pcbextrude "PCBExtrude"
pcbextrude "PCBExtrude1"
derived_base_feature "pcb-sketch"
derived_base_feature "Base Feature"
box_primitive "BoxPrimitive1" DistanceX 8 DistanceY 3.81 DistanceZ 0.1 OffsetDistanceX 0 OffsetDistanceY 0
base_feature "Base Feature"
box_primitive "BoxPrimitive1" DistanceX 20 DistanceY 17.95 DistanceZ 1 OffsetDistanceX 0 OffsetDistanceY 0
pcbextrude "PCBExtrude1"
pcbextrude "PCBExtrude1"
extrude "Extrude1" sketch "pcb-sketch" blind 1.5 bodies "Board"
pcbextrude "PCBExtrude1"
pcbextrude "PCBExtrude"
create_component "CreateComponent1"
create_component "CreateComponent2"
create_component "CreateComponent3"
create_component "CreateComponent4"
create_component "CreateComponent5"
create_component "CreateComponent6"
create_component "CreateComponent3"
as_built_joint "As-built1"
create_component "CreateComponent5"
create_component "CreateComponent6"
step "CreateComponent"
named bodies: "Board"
